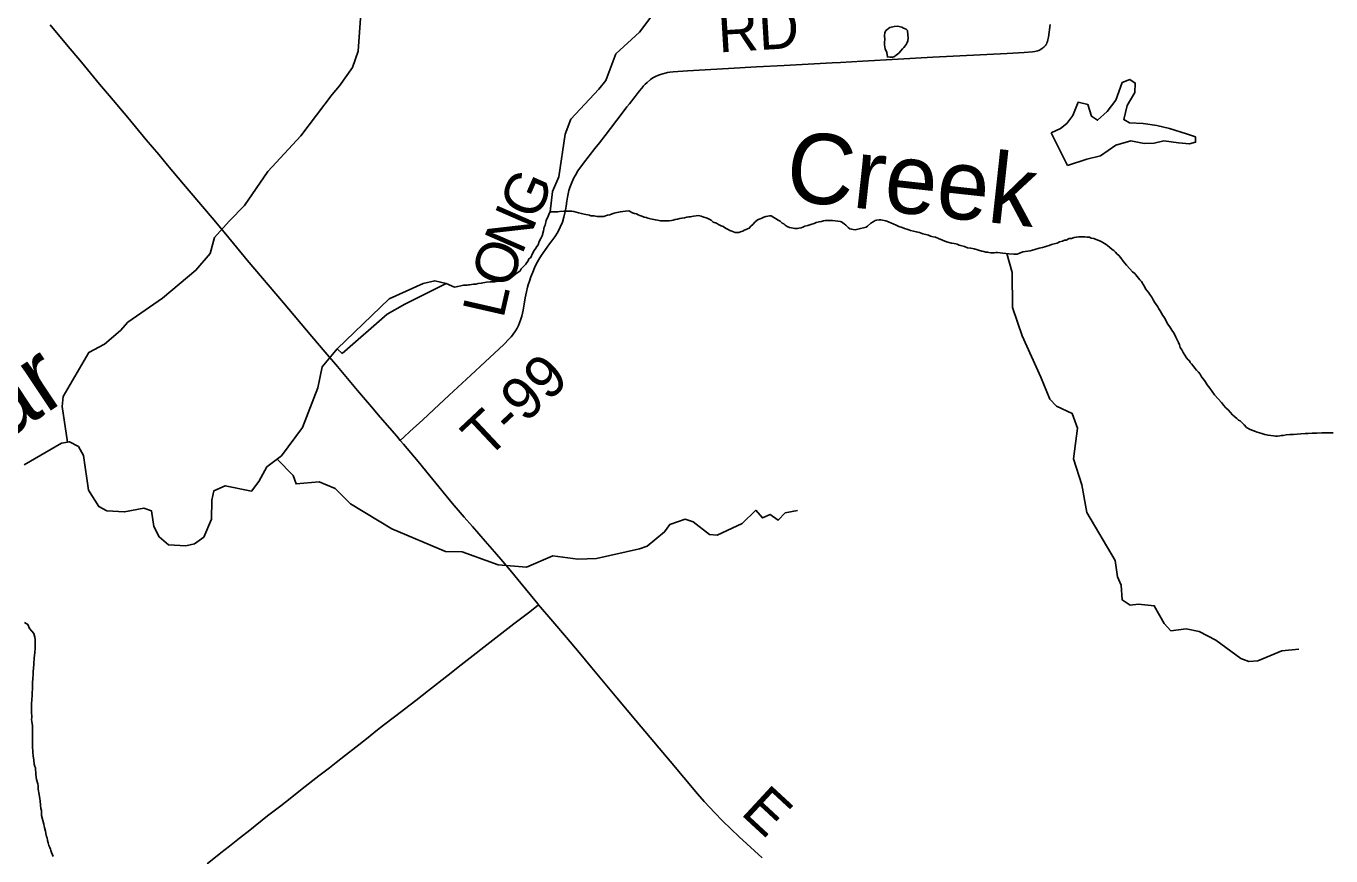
# Model space of a CAD drawing. Extents: x 1410790 to 1770854, y 448063 to 770588.
# Drawn here: x 1586619 to 1595915, y 598046 to 603957 of the extents above; entities that cross this region are included whole.
import ezdxf

# ---------------------------------------------------------------- set-up
doc = ezdxf.new("R2010")
doc.units = 0
for name, color, linetype in [('GM_X_County_Road', 7, 'Continuous'), ('GM_X_County_Road_Text', 7, 'Continuous'), ('GM_X_Major_River', 7, 'Continuous'), ('GM_X_Major_River_Text', 7, 'Continuous'), ('GM_X_Minor_Lake', 7, 'Continuous'), ('GM_X_Minor_River', 7, 'Continuous'), ('GM_X_Township_Road', 7, 'Continuous'), ('GM_X_Township_Road_Text', 7, 'Continuous')]:
    doc.layers.add(name, color=color, linetype=linetype)

msp = doc.modelspace()

# ---------------------------------------------------------------- linework, layer by layer
at = {"layer": 'GM_X_County_Road'}
for points in [[(1589284.6, 601005.3), (1589259, 601035), (1589142.2, 601171.9), (1589080.8, 601244.3), (1588980.9, 601361.8), (1588837.5, 601532.7), (1588750.6, 601635.2), (1588654.2, 601747.1), (1588453.4, 601985.4), (1588194.7, 602290.9), (1588041.5, 602475), (1587945.2, 602591.1), (1587741.4, 602830.7), (1587627.1, 602966), (1587564, 603041.4), (1587474.3, 603146), (1587342.6, 603305.3), (1587212.2, 603461.2), (1587142.4, 603543.9), (1587013.1, 603700.4), (1586906.8, 603825.2), (1586789.8, 603966.8)], [(1590270.5, 599833.8), (1590263.9, 599841.6), (1590209.9, 599907.6), (1590144.6, 599989.4), (1590079.6, 600067.3), (1590015.9, 600142.3), (1589956, 600211.8), (1589889, 600288.2), (1589798.7, 600391.9), (1589740.6, 600458.7), (1589655.3, 600558.6), (1589494.6, 600753.5), (1589411.1, 600854.8), (1589308.1, 600978), (1589284.6, 601005.3)], [(1591862.7, 598030.9), (1591698.1, 598181.5), (1591579.6, 598295.2), (1591524.6, 598351.7), (1591448.9, 598433.8), (1591401.6, 598488.4), (1591207.8, 598719.9), (1591129.5, 598812.6), (1590962.4, 599010.6), (1590827.8, 599171.7), (1590648.3, 599385), (1590558.6, 599493.9), (1590467.9, 599601.9), (1590372.4, 599714.4), (1590270.5, 599833.8)]]:
    msp.add_lwpolyline(points, dxfattribs=at)
at = {"layer": 'GM_X_Major_River'}
for points in [[(1590352.2, 602635.2), (1590405.5, 602633.2), (1590419.6, 602637.1), (1590449.7, 602638.8), (1590481.7, 602638.4), (1590505.8, 602638.2), (1590521.8, 602636), (1590553.8, 602627.7), (1590575.7, 602621.4), (1590595.7, 602617.2), (1590631.7, 602610.8), (1590641.7, 602606.7), (1590653.7, 602606.6), (1590665.7, 602604.4), (1590675.7, 602602.3), (1590687.7, 602600.2), (1590699.7, 602600.1), (1590715.8, 602599.9), (1590725.8, 602601.8), (1590735.8, 602601.7), (1590747.9, 602605.6), (1590762, 602609.5), (1590778, 602613.3), (1590794.1, 602619.2), (1590808.2, 602625), (1590828.3, 602628.8), (1590842.4, 602632.7), (1590852.4, 602634.6), (1590870.5, 602636.4), (1590888.5, 602638.2), (1590912.6, 602640), (1590938.5, 602627.7), (1590954.5, 602621.5), (1590968.5, 602619.3), (1590980.4, 602613.2), (1590990.4, 602609.1), (1591004.4, 602602.9), (1591022.3, 602596.7), (1591036.3, 602592.6), (1591048.3, 602588.4), (1591066.3, 602584.2), (1591102.3, 602575.9), (1591116.3, 602573.7), (1591128.3, 602571.6), (1591140.3, 602569.4), (1591152.3, 602569.3), (1591168.3, 602569.2), (1591184.3, 602569), (1591200.4, 602570.8), (1591216.4, 602572.7), (1591228.5, 602574.5), (1591242.6, 602578.4), (1591260.6, 602582.2), (1591276.7, 602586.1), (1591290.7, 602587.9), (1591308.8, 602591.8), (1591326.9, 602595.6), (1591340.9, 602597.4), (1591351, 602597.3), (1591373.1, 602603.1), (1591393.1, 602604.9), (1591409.2, 602606.8), (1591427.2, 602602.6), (1591441.1, 602598.4), (1591471.1, 602590.1), (1591485, 602581.9), (1591499, 602573.8), (1591514.9, 602561.5), (1591536.8, 602553.3), (1591552.8, 602543.1), (1591570.7, 602534.9), (1591584.7, 602528.8), (1591594.6, 602522.6), (1591606.6, 602516.5), (1591620.5, 602508.3), (1591632.5, 602502.2), (1591646.5, 602496), (1591658.4, 602491.9), (1591670.4, 602487.8), (1591680.4, 602487.7), (1591696.5, 602487.5), (1591708.5, 602491.4), (1591724.6, 602497.2), (1591734.7, 602503.1), (1591748.8, 602509), (1591758.9, 602512.9), (1591770.9, 602518.8), (1591783.1, 602532.7), (1591795.3, 602544.6), (1591811.5, 602560.5), (1591829.7, 602576.3), (1591847.8, 602584.2), (1591859.9, 602590.1), (1591873.9, 602595.9), (1591888, 602601.8), (1591902.1, 602603.7), (1591914.1, 602605.5), (1591926.1, 602605.4), (1591977.9, 602574.8), (1591991.9, 602566.6), (1592005.8, 602554.5)], [(1589610.6, 602123.7), (1589670.5, 602097.4), (1589694.6, 602103.1), (1589716.7, 602106.9), (1589734.8, 602110.8), (1589750.8, 602110.6), (1589760.9, 602112.5), (1589770.9, 602114.4), (1589780.9, 602114.3), (1589793, 602116.2), (1589807, 602118), (1589823, 602119.9), (1589839.1, 602123.7), (1589861.2, 602125.5), (1589873.2, 602129.4), (1589887.3, 602131.2), (1589899.3, 602133.1), (1589925.4, 602134.8), (1589941.4, 602134.7), (1589957.5, 602134.5), (1589983.6, 602140.2), (1590007.6, 602144), (1590021.7, 602145.9), (1590035.8, 602151.7), (1590049.9, 602157.6), (1590064, 602163.5), (1590078.1, 602171.4), (1590090.2, 602177.2), (1590110.4, 602195.1), (1590128.5, 602206.9), (1590138.6, 602212.8), (1590146.8, 602226.8), (1590156.9, 602238.7), (1590169.1, 602250.6), (1590179.2, 602260.6), (1590187.3, 602272.5), (1590195.5, 602284.4), (1590201.6, 602298.4), (1590215.8, 602308.3), (1590226.1, 602336.3), (1590238.3, 602358.2), (1590250.5, 602374.1), (1590258.7, 602388.1), (1590266.8, 602398), (1590275.1, 602422), (1590287.4, 602447.9), (1590295.5, 602461.9), (1590303.9, 602497.9), (1590310.2, 602523.9), (1590316.4, 602539.9), (1590324.7, 602571.9), (1590337.1, 602603.8), (1590347.3, 602625.8), (1590352.2, 602635.2)], [(1592005.8, 602554.5), (1592017.7, 602548.3), (1592027.6, 602538.2), (1592041.6, 602530), (1592057.5, 602521.8), (1592071.5, 602519.7), (1592083.5, 602517.6), (1592095.5, 602515.4), (1592113.6, 602515.2), (1592123.6, 602517.2), (1592139.7, 602521), (1592153.7, 602524.9), (1592167.8, 602532.7), (1592187.9, 602536.5), (1592202, 602542.4), (1592216.1, 602546.3), (1592232.2, 602552.1), (1592248.3, 602558), (1592268.4, 602563.8), (1592286.4, 602565.6), (1592300.5, 602569.5), (1592312.5, 602571.3), (1592328.6, 602573.2), (1592346.6, 602573), (1592364.6, 602572.8), (1592382.7, 602570.6), (1592402.7, 602568.4), (1592418.7, 602566.2), (1592428.7, 602562.1), (1592446.5, 602547.9), (1592458.5, 602539.8), (1592476.3, 602523.5), (1592488.3, 602513.4), (1592500.3, 602511.2), (1592512.2, 602507.1), (1592526.3, 602507), (1592544.3, 602510.8), (1592602.6, 602524.2), (1592612.7, 602532.1), (1592637, 602553.9), (1592653.1, 602563.8), (1592667.2, 602571.7), (1592679.3, 602575.6), (1592697.3, 602577.4), (1592707.3, 602577.3), (1592719.3, 602575.2), (1592731.3, 602573), (1592743.3, 602568.9), (1592763.3, 602562.7), (1592783.3, 602554.4), (1592797.2, 602548.3), (1592817.1, 602538), (1592837.1, 602529.8), (1592859.1, 602521.6), (1592877, 602515.4), (1592893, 602511.2), (1592907, 602507), (1592918.9, 602500.9), (1592940.9, 602496.6), (1592960.9, 602492.4), (1592982.9, 602486.2), (1593006.9, 602477.9), (1593028.9, 602471.7), (1593046.8, 602467.5), (1593062.8, 602461.3), (1593080.8, 602457.1), (1593098.8, 602452.9), (1593118.7, 602444.7), (1593146.7, 602432.3), (1593176.6, 602420), (1593212.6, 602411.6), (1593230.6, 602409.4), (1593242.6, 602405.3), (1593252.6, 602403.2), (1593266.5, 602397), (1593284.5, 602392.8), (1593304.5, 602386.6), (1593326.4, 602378.3), (1593348.4, 602374.1), (1593372.4, 602369.8), (1593428.4, 602353.2), (1593442.4, 602351.1), (1593456.4, 602346.9), (1593468.4, 602346.8), (1593478.4, 602344.7), (1593492.4, 602342.5), (1593506.4, 602342.4), (1593516.4, 602342.3), (1593528.5, 602344.2), (1593538.5, 602344), (1593578.5, 602339.6), (1593620.6, 602335.2), (1593656.6, 602332.8), (1593678.6, 602332.6), (1593690.7, 602336.5), (1593720.9, 602348.2), (1593771.1, 602355.7), (1593805.2, 602365.3), (1593837.4, 602375), (1593859.5, 602378.8), (1593875.6, 602384.7)], [(1593875.6, 602384.7), (1593891.7, 602390.5), (1593907.7, 602394.4), (1593923.8, 602400.2), (1593943.9, 602406), (1593964, 602411.8), (1593982.1, 602419.7), (1594002.2, 602425.5), (1594016.3, 602431.3), (1594028.4, 602433.2), (1594050.5, 602443), (1594066.6, 602444.8), (1594084.7, 602450.7), (1594100.7, 602452.5), (1594120.8, 602456.3), (1594142.8, 602456.1), (1594160.9, 602455.9), (1594176.9, 602453.7), (1594194.9, 602453.5), (1594206.9, 602447.4), (1594224.9, 602443.2), (1594242.8, 602437), (1594260.8, 602428.8), (1594276.8, 602422.6), (1594290.7, 602416.4), (1594300.7, 602408.3), (1594312.6, 602402.2), (1594326.5, 602392), (1594338.4, 602381.8), (1594356.3, 602365.6), (1594368.3, 602357.5), (1594380.2, 602347.3), (1594390.1, 602335.2), (1594404, 602323), (1594417.8, 602306.8), (1594435.6, 602282.6), (1594457.3, 602254.3), (1594481.1, 602228), (1594500.9, 602207.7), (1594516.8, 602195.5), (1594524.7, 602185.4), (1594552.4, 602149), (1594564.3, 602136.9), (1594572.2, 602126.8), (1594578.1, 602116.7), (1594584, 602106.6), (1594593.8, 602086.4), (1594605.7, 602070.2), (1594617.6, 602058.1), (1594625.5, 602044), (1594639.3, 602025.8), (1594649.1, 602007.6), (1594659, 601991.5), (1594670.8, 601973.3), (1594680.7, 601957.2), (1594688.5, 601943), (1594698.4, 601928.9), (1594708.2, 601912.8), (1594718.1, 601894.6), (1594729.9, 601878.4), (1594741.7, 601858.3), (1594751.5, 601836.1), (1594767.3, 601813.9), (1594781.1, 601791.7), (1594792.9, 601773.5), (1594802.8, 601757.4), (1594810.6, 601741.2), (1594818.5, 601723.1), (1594828.3, 601703), (1594836.1, 601686.8), (1594841.9, 601668.7), (1594851.8, 601650.6), (1594861.6, 601632.4), (1594873.4, 601612.2), (1594885.3, 601594.1), (1594897.1, 601579.9), (1594907.1, 601571.8), (1594913, 601561.7), (1594920.9, 601551.6), (1594932.7, 601537.4), (1594944.6, 601521.3), (1594956.5, 601507.1), (1594970.3, 601490.9), (1594982.2, 601476.8), (1594992, 601458.6), (1595007.9, 601442.4), (1595019.8, 601426.2), (1595033.5, 601402), (1595051.3, 601377.8), (1595069.1, 601353.5), (1595084.9, 601329.3), (1595136.4, 601274.6), (1595150.2, 601256.4), (1595166.1, 601238.2), (1595183.9, 601220), (1595197.8, 601205.8), (1595213.6, 601187.6), (1595229.5, 601173.4), (1595245.4, 601161.2), (1595257.3, 601149), (1595267.3, 601144.9)], [(1588836, 601656.9), (1589204.5, 602013.6), (1589447.2, 602124.4), (1589529.7, 602142.7), (1589610.5, 602123.7)], [(1588871.6, 601624.2), (1589190.1, 601905.7), (1589317.8, 601977), (1589610.6, 602123.7)], [(1586606, 600832.4), (1586871.6, 600984.9), (1586927.9, 600995.7), (1586991.2, 600962.2), (1587027.8, 600897.3), (1587062.4, 600652.1), (1587137.8, 600534.3), (1587193.2, 600503), (1587321.1, 600496.2), (1587457.9, 600523.2), (1587511.5, 600504), (1587529, 600391.5), (1587567.4, 600318.5), (1587634.2, 600262.9), (1587756.1, 600254.2), (1587818.5, 600268.9), (1587885.6, 600317.5), (1587940.5, 600444.5), (1587941.5, 600580.8), (1587957, 600646.5), (1588037.9, 600682.8), (1588225.2, 600644.7), (1588276.8, 600713.6), (1588335.1, 600816.5), (1588439, 600896.4), (1588587.6, 601097.5), (1588698, 601379.6), (1588727.3, 601529.2), (1588836, 601656.9)], [(1588871.6, 601624.2), (1588836, 601656.9)], [(1595267.3, 601144.9), (1595277.2, 601134.8), (1595297, 601116.5), (1595312.9, 601098.3), (1595338.8, 601084), (1595358.7, 601075.8), (1595376.7, 601069.6), (1595388.7, 601063.4), (1595406.7, 601059.2), (1595422.7, 601055), (1595444.6, 601048.8), (1595466.6, 601042.6), (1595486.6, 601040.3), (1595504.6, 601038.2), (1595520.6, 601036), (1595534.7, 601035.8), (1595550.7, 601037.7), (1595560.8, 601039.6), (1595574.8, 601041.4), (1595596.9, 601045.2), (1595623, 601046.9), (1595649, 601048.7), (1595675.1, 601050.4), (1595701.2, 601052.1), (1595731.3, 601053.8), (1595753.3, 601055.6), (1595781.4, 601057.3), (1595815.4, 601056.9), (1595849.5, 601058.6), (1595879.6, 601060.3), (1595905.7, 601060), (1595929.7, 601059.8)]]:
    msp.add_lwpolyline(points, dxfattribs=at)
at = {"layer": 'GM_X_Minor_Lake'}
for points in [[(1592741.5, 603924.5), (1592771.8, 603948.2), (1592804, 603953.9), (1592830, 603955.7), (1592858, 603949.4), (1592870, 603943.2), (1592887.9, 603935), (1592897.8, 603924.9), (1592899.5, 603894.8), (1592903.3, 603872.7), (1592901.1, 603852.7), (1592894.9, 603840.7), (1592888.8, 603826.7), (1592880.7, 603816.8), (1592872.5, 603804.8), (1592862.4, 603794.9), (1592850.2, 603781), (1592836, 603765.1), (1592817.8, 603749.2), (1592805.7, 603741.3), (1592793.7, 603735.5), (1592773.6, 603735.7), (1592755.6, 603737.8), (1592749.9, 603770), (1592738.2, 603794.2), (1592734.5, 603824.3), (1592734.7, 603844.4), (1592736.8, 603860.4), (1592735.2, 603890.5), (1592737.4, 603908.5), (1592741.5, 603920.5), (1592741.5, 603924.5)], [(1594038.9, 602963.2), (1594175.8, 603009.2), (1594274.3, 603033.8), (1594381.5, 603108.3), (1594490.1, 603138.7), (1594583.9, 603121.2), (1594656.1, 603124.2), (1594724.4, 603139.1), (1594828.3, 603125.5), (1594906.3, 603118.3), (1594950.5, 603129.7), (1594949.1, 603167.8), (1594885.4, 603190.8), (1594765.8, 603226.7), (1594674, 603250.1), (1594576.1, 603263.6), (1594480.1, 603269.1), (1594440.4, 603291.8), (1594462, 603391.6), (1594517.4, 603485), (1594520.5, 603551), (1594482.8, 603577.7), (1594426.4, 603554.5), (1594382.4, 603428.9), (1594321.1, 603347.7), (1594252.1, 603286.6), (1594208.5, 603315.3), (1594183.7, 603397.8), (1594113.9, 603414.9), (1594076.4, 603321.3), (1594033.5, 603263.9), (1593988.9, 603228.5), (1593922.4, 603197.4)], [(1593922.4, 603197.4), (1594038.9, 602963.2)]]:
    msp.add_lwpolyline(points, dxfattribs=at)
at = {"layer": 'GM_X_Minor_River'}
for points in [[(1590352.2, 602635.2), (1590370, 602778.3), (1590413.7, 602883.9), (1590460.4, 603187.8), (1590500.1, 603295.4), (1590699.6, 603508.8), (1590748.6, 603570.2), (1590821.5, 603759.4), (1590990.1, 603913.2), (1591084.1, 604040)], [(1586914.4, 600993.1), (1586876.8, 601248.1), (1586881.9, 601318.2), (1587064.9, 601632), (1587178, 601692.4), (1587291.6, 601788.9), (1587344.5, 601848.2), (1587591.4, 602018.8), (1587828.7, 602217.6), (1587930.6, 602336.3), (1587960.4, 602450.1), (1588066.3, 602566.7), (1588174.1, 602679.3), (1588340, 602921.3), (1588576.2, 603176.2), (1588798.9, 603469.4), (1588851.9, 603532.7), (1588944, 603661.6), (1588983.8, 603779.2), (1589001.4, 604013.4)], [(1593606.6, 602336.1), (1593644.8, 602201.7), (1593647, 601953.1), (1593716, 601749.7), (1593847.7, 601457.1), (1593913.3, 601299.8), (1593958.6, 601249), (1594071.9, 601197.2), (1594108.4, 601092.4), (1594081, 600874.4), (1594140.2, 600689.2), (1594175.3, 600492.2), (1594378.3, 600150.5), (1594394.5, 600034), (1594421.6, 599975.5), (1594428, 599869.2), (1594485.5, 599832.2), (1594543.7, 599839.4), (1594655.6, 599827.6), (1594725.8, 599702.3), (1594775, 599649.5), (1594883.4, 599663.8), (1594975.2, 599644.4), (1595094.4, 599582.5), (1595272.6, 599451.5), (1595330.3, 599430.6), (1595394.5, 599435.6), (1595565.8, 599507.2), (1595686.1, 599517.4)], [(1588408.4, 600872.9), (1588521.1, 600756.3), (1588542.2, 600695.8), (1588706.6, 600709.4), (1588820, 600663.6), (1588930.4, 600553.7), (1589224, 600374.9), (1589608, 600214.8), (1589726.1, 600211), (1589982.9, 600118.9), (1590182.9, 600101.9), (1590372.3, 600183.2), (1590550.2, 600160.4), (1590682.4, 600164.5), (1590989.8, 600233.9), (1591044.1, 600253.2), (1591098.9, 600296.4), (1591167.8, 600353.5), (1591204.7, 600407), (1591313.3, 600443.5), (1591371.1, 600426.6), (1591487.9, 600334.6), (1591541.9, 600329.8), (1591719.3, 600413.3), (1591816.9, 600508), (1591864.1, 600453.2), (1591920.5, 600478.3), (1591976, 600437.4), (1592026.8, 600488.8), (1592115.2, 600505.5)], [(1586607.7, 599708.7), (1586619.6, 599700.5), (1586631.6, 599694.4), (1586643.3, 599666.2), (1586659.1, 599646), (1586673, 599629.8), (1586680.7, 599603.7), (1586682.6, 599587.6), (1586684.4, 599569.5), (1586684.3, 599557.5), (1586684.1, 599545.5), (1586684, 599533.4), (1586683.9, 599523.4), (1586681.6, 599495.4), (1586679.4, 599473.3), (1586677.2, 599457.3), (1586677, 599441.3), (1586674.9, 599429.2), (1586674.7, 599409.2), (1586672.4, 599383.2), (1586670.1, 599357.1), (1586669.9, 599335.1), (1586667.7, 599313), (1586667.5, 599299), (1586665.4, 599289), (1586665.3, 599274.9), (1586665, 599252.9), (1586664.8, 599232.8), (1586662.6, 599210.8), (1586662.4, 599190.8)], [(1586662.4, 599190.8), (1586660, 599156.7), (1586657.7, 599128.6), (1586657.6, 599114.6), (1586657.5, 599102.6), (1586657.3, 599090.5), (1586657.2, 599074.5), (1586658.7, 599032.4), (1586658.6, 599018.3), (1586660.4, 599002.3), (1586662.2, 598986.2), (1586664.1, 598974.2), (1586663.7, 598934.1), (1586665.6, 598924), (1586665.5, 598912), (1586665.4, 598902), (1586665.2, 598887.9), (1586665, 598869.9), (1586664.8, 598849.8), (1586664.6, 598827.8), (1586666.1, 598785.6), (1586669.8, 598755.5), (1586673.6, 598729.4), (1586677.3, 598699.3), (1586681.1, 598683.2), (1586685, 598673.2), (1586688.5, 598625), (1586694.1, 598588.8), (1586701.8, 598558.7), (1586705.7, 598544.6), (1586705.4, 598520.5), (1586711.1, 598482.4), (1586716.8, 598452.2), (1586718.6, 598438.2), (1586722.3, 598408.1), (1586724.1, 598384), (1586727.9, 598367.9), (1586729.5, 598333.8), (1586737.2, 598297.6), (1586744.9, 598271.5), (1586748.8, 598257.4), (1586750.7, 598247.3), (1586756.4, 598221.2), (1586760.3, 598205.1), (1586764.1, 598185), (1586767.9, 598175), (1586771.7, 598154.9), (1586775.6, 598138.8), (1586781.4, 598118.7), (1586787.3, 598106.6), (1586793.1, 598094.5), (1586795, 598084.5), (1586798.9, 598070.4), (1586806.7, 598052.3), (1586812.6, 598042.2)]]:
    msp.add_lwpolyline(points, dxfattribs=at)
at = {"layer": 'GM_X_Township_Road'}
for points in [[(1589284.6, 601005.3), (1589312.5, 601030.9), (1589353.7, 601068.6), (1589444.9, 601153.4), (1589524.3, 601226.8), (1589632.5, 601327.3), (1589786.7, 601469.7), (1589889.7, 601566.1), (1590021.4, 601689.5), (1590061.4, 601728.7), (1590074.4, 601742.9), (1590085, 601756.6), (1590106, 601786.5), (1590116.6, 601804.8), (1590126.4, 601825), (1590134, 601842.5), (1590143.5, 601869), (1590149.7, 601890), (1590155.2, 601912.1), (1590159.8, 601933.5), (1590166.8, 601976), (1590175, 602021.1), (1590184.4, 602065.1), (1590191.7, 602096.6), (1590196.8, 602114.9), (1590205, 602140.5), (1590215.4, 602172.1), (1590228.1, 602204.4), (1590240.5, 602234.5), (1590253, 602261), (1590271.5, 602295.5), (1590289.7, 602325.5), (1590330.3, 602382.6), (1590348.2, 602405.8), (1590364.5, 602427.5), (1590385.8, 602456.9), (1590406.7, 602490), (1590424.3, 602524.7), (1590439.3, 602561.6), (1590449.9, 602596.4), (1590461.7, 602645.5), (1590466, 602673.8), (1590471.3, 602709.6), (1590475.9, 602738.5), (1590480.4, 602762.5), (1590485.2, 602785.5), (1590492.4, 602808.1), (1590505.9, 602843.9), (1590520.9, 602875.8), (1590532.2, 602895.4), (1590550.7, 602926), (1590590.7, 602981.7), (1590671, 603085.3), (1590703.5, 603126.5), (1590743.9, 603178.1), (1590866, 603336.6), (1590899.6, 603381), (1590917.3, 603404.5), (1590957, 603456.2), (1590978.7, 603484.7), (1591014.2, 603526.7), (1591018.6, 603531.4), (1591030.1, 603542.8), (1591044.2, 603556.1), (1591068.1, 603576.3), (1591084.2, 603587.5), (1591103.4, 603598.7), (1591123.2, 603607.3), (1591139.7, 603613.1), (1591156.1, 603618.1), (1591187.6, 603625.5), (1591204.4, 603628.6), (1591229.4, 603631.6), (1591330.6, 603638.9), (1591624.1, 603655.1), (1591822.7, 603666.1), (1592020, 603676.9), (1592361, 603694.8), (1592419.8, 603698.3), (1592576.9, 603707.4), (1592832, 603722.8), (1593077.7, 603735.5), (1593608.4, 603762.5), (1593729.7, 603769), (1593788.9, 603773.4), (1593804.2, 603775.4), (1593814.6, 603777.6), (1593825.3, 603780.9), (1593833.6, 603784.3), (1593842.7, 603788.3), (1593849.1, 603791.9), (1593856.8, 603797), (1593863.2, 603802.3), (1593869.3, 603807.5), (1593875.9, 603814.1), (1593881.6, 603820.1), (1593884.9, 603824.4), (1593888, 603829.2), (1593892, 603837.8), (1593895.9, 603847.3), (1593899, 603859.5), (1593902.4, 603879.5), (1593913.8, 603967.8)], [(1587908.4, 597990.1), (1588006, 598066.8), (1588067.7, 598115.6), (1588139.8, 598172.5), (1588211.9, 598229.3), (1588339.9, 598331.6), (1588433.5, 598403.4), (1588500.8, 598455.7), (1588585.4, 598523.1), (1588704.6, 598615.5), (1588779.9, 598673.6), (1588829, 598711.9), (1588893.7, 598762.2), (1588968.4, 598820.8), (1589043.2, 598879.7), (1589122.9, 598942.7), (1589166.3, 598977.7), (1589244.5, 599037.4), (1589395.1, 599153.7), (1589486.4, 599223.2), (1589625.5, 599332.8), (1589718.3, 599405.7), (1589965.9, 599600.2), (1590092.9, 599698.7), (1590197.6, 599778), (1590244.4, 599813.8), (1590270.5, 599833.8)]]:
    msp.add_lwpolyline(points, dxfattribs=at)

# ---------------------------------------------------------------- texts
at = {"layer": 'GM_X_County_Road_Text'}
msp.add_text('E', height=300, rotation=317.22787, dxfattribs=at).set_placement((1591702.2, 598346.9))
at = {"layer": 'GM_X_Major_River_Text'}
for s, height, rotation, p in [('Creek', 499.99, 353.7806, (1592016.3, 602718.6)), ('Caesar', 499.97, 33.65649, (1585147.8, 600121.6))]:
    msp.add_text(s, height=height, rotation=rotation, dxfattribs=at).set_placement(p)
at = {"layer": 'GM_X_Township_Road_Text'}
for s, rotation, p in [('RD', 3.42219, (1591554.2, 603769.1)), ('G', 66.2561, (1590255.5, 602563.4)), ('N', 66.38814, (1590149.9, 602321.7)), ('O', 70.93722, (1590065.9, 602078)), ('L', 77.12487, (1590018.3, 601867.5)), ('T-99', 43.27978, (1589900, 600864.3))]:
    msp.add_text(s, height=300, rotation=rotation, dxfattribs=at).set_placement(p)

doc.saveas('drawing.dxf')
